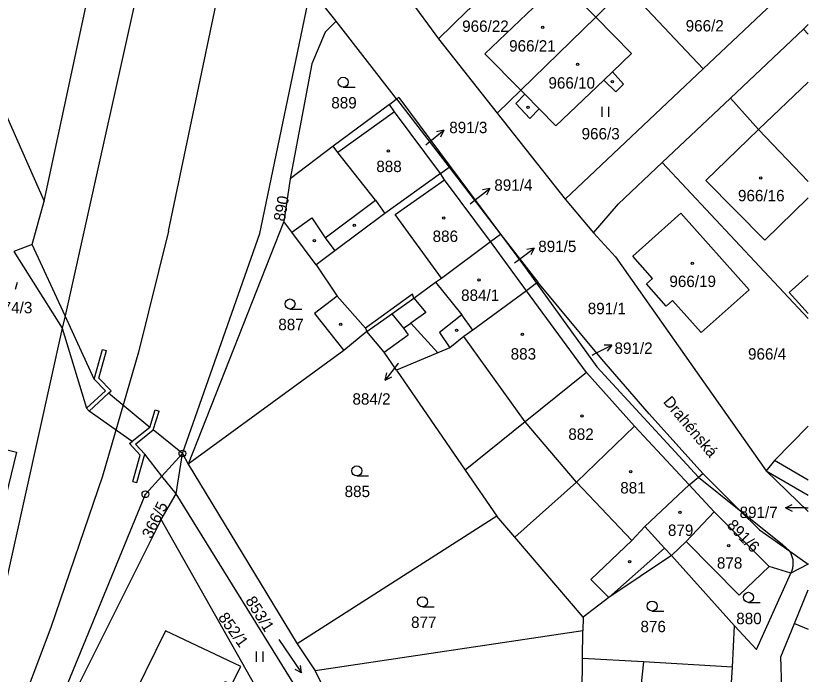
# Model space of a CAD drawing. Extents: x -776606 to -776076, y -974328 to -973875.
# Drawn here: x -776193.8 to -776075.5, y -974047.1 to -973948.9 of the extents above; entities that cross this region are included whole.
import ezdxf

# ---------------------------------------------------------------- set-up
doc = ezdxf.new("R2010")
doc.units = 0
for name, color, linetype in [('Hranice parcel', 7, 'Continuous'), ('Parcelní čísla', 7, 'Continuous'), ('Pop  PČ popisy', 7, 'Continuous'), ('Poz předměty', 7, 'Continuous'), ('Vnitřní kresba', 7, 'Continuous'), ('Značky bodu BP', 7, 'Continuous'), ('Značky budov', 7, 'Continuous'), ('Značky kultur', 7, 'Continuous')]:
    doc.layers.add(name, color=color, linetype=linetype)

msp = doc.modelspace()

# ---------------------------------------------------------------- linework, layer by layer
at = {"layer": 'Hranice parcel'}
for p, q in [((-776189.59, -973976.54), (-776179.58, -973929.94)), ((-776076.65, -973943.02), (-776091.19, -973956.75)), ((-776145.99, -973949.66), (-776149.78, -973944.77)), ((-776136.26, -973944.7), (-776130.7, -973952.3)), ((-776102.68, -973944.59), (-776107.23, -973949.03)), ((-776102.68, -973944.59), (-776091.19, -973956.75)), ((-776107.23, -973949.03), (-776118.42, -973959.96)), ((-776136.96, -973961.25), (-776145.99, -973949.66)), ((-776076.22, -973950.83), (-776075.52, -973950.16)), ((-776087.12, -973961.13), (-776076.22, -973950.83)), ((-776075.52, -973951.58), (-776076.22, -973950.83)), ((-776130.7, -973952.3), (-776121.93, -973963.39)), ((-776091.19, -973956.75), (-776111.8, -973976.22)), ((-776118.42, -973959.96), (-776121.93, -973963.39)), ((-776138, -973962.1), (-776136.96, -973961.25)), ((-776136.96, -973961.25), (-776129.11, -973971.44)), ((-776097.3, -973970.74), (-776087.12, -973961.13)), ((-776082.92, -973965.84), (-776087.12, -973961.13)), ((-776121.93, -973963.39), (-776111.8, -973976.22)), ((-776075.52, -973973.58), (-776082.92, -973965.84)), ((-776075.52, -973994.02), (-776097.3, -973970.74)), ((-776130.42, -973972.41), (-776129.11, -973971.44)), ((-776129.11, -973971.44), (-776121.45, -973981.44)), ((-776152.87, -973973.18), (-776153.8, -973979.55)), ((-776111.8, -973976.22), (-776107.56, -973981.25)), ((-776153.8, -973979.55), (-776168.07, -974015.77)), ((-776122.96, -973982.56), (-776121.45, -973981.44)), ((-776121.45, -973981.44), (-776115.88, -973988.61)), ((-776117.59, -973989.89), (-776122.96, -973982.56)), ((-776194.09, -973984.05), (-776186.87, -973995.48)), ((-776116.06, -973988.75), (-776117.59, -973989.89)), ((-776115.88, -973988.61), (-776116.06, -973988.75)), ((-776108.62, -974002.09), (-776117.59, -973989.89)), ((-776186.46, -973993.62), (-776186.87, -973995.48)), ((-776141.42, -973995.98), (-776137.69, -973993.34)), ((-776137.69, -973993.34), (-776135.91, -973995.5)), ((-776141.42, -973995.98), (-776144.84, -973998.83)), ((-776144.84, -973998.83), (-776168.07, -974015.77)), ((-776130.82, -973999.16), (-776136.99, -974001.76)), ((-776136.99, -974001.76), (-776126.7, -974016.67)), ((-776101.42, -974010.12), (-776108.62, -974002.09)), ((-776093.3, -974018.87), (-776101.42, -974010.12)), ((-776171.99, -974017.55), (-776168.94, -974014.19)), ((-776169.88, -974020.23), (-776168.94, -974014.19)), ((-776168.94, -974014.19), (-776168.07, -974015.77)), ((-776168.07, -974015.77), (-776151.82, -974042.59)), ((-776126.7, -974016.67), (-776121.97, -974023.54)), ((-776081.8, -974016.78), (-776075.52, -974020.41)), ((-776089.54, -974022.91), (-776093.3, -974018.87)), ((-776172.13, -974024.06), (-776169.88, -974020.23)), ((-776172.13, -974024.06), (-776193.76, -974067.27)), ((-776148.31, -974066.12), (-776172.13, -974024.06)), ((-776121.97, -974023.54), (-776151.82, -974042.59)), ((-776119.31, -974026.66), (-776121.97, -974023.54)), ((-776089.54, -974022.91), (-776093.73, -974027.35)), ((-776081.36, -974031.08), (-776089.54, -974022.91)), ((-776109.12, -974038.61), (-776119.31, -974026.66)), ((-776095.9, -974029.4), (-776093.73, -974027.35)), ((-776086.53, -974039.94), (-776095.9, -974029.4)), ((-776078.09, -974032.03), (-776081.36, -974031.08)), ((-776075.53, -974030.69), (-776078.09, -974032.03)), ((-776075.52, -974030.68), (-776075.53, -974030.69)), ((-776109.12, -974038.61), (-776109.14, -974040.66)), ((-776086.8, -974046.07), (-776086.53, -974039.94)), ((-776109.14, -974040.66), (-776149.12, -974046.61)), ((-776109.18, -974044.78), (-776109.14, -974040.66)), ((-776151.82, -974042.59), (-776149.12, -974046.61)), ((-776109.25, -974051.62), (-776109.18, -974044.78)), ((-776087.23, -974052.97), (-776086.8, -974046.07)), ((-776149.12, -974046.61), (-776143.9, -974057.28))]:
    msp.add_line(p, q, dxfattribs=at)
for points in [[(-776213.8, -973922.1), (-776202.27, -973939.42), (-776200.89, -973951.06), (-776189.59, -973976.54)], [(-776167.74, -973928.46), (-776173.47, -973935.17), (-776186.46, -973993.62)], [(-776130.7, -973952.3), (-776126.49, -973948.15), (-776111.76, -973934.97)], [(-776168.94, -974014.19), (-776157.37, -973981.34), (-776149.78, -973944.77)], [(-776107.23, -973949.03), (-776112.46, -973943.72), (-776115.35, -973946.49), (-776116.81, -973945.05), (-776117.87, -973946.03), (-776116.47, -973947.55), (-776123.77, -973954.53), (-776118.42, -973959.96)], [(-776107.23, -973949.03), (-776101.87, -973954.48), (-776104.75, -973957.23), (-776103.06, -973959.05), (-776104.22, -973960.21), (-776106.02, -973958.45), (-776113.17, -973965.28), (-776115.67, -973962.75), (-776117.06, -973964.17), (-776119.17, -973961.92), (-776117.83, -973960.56), (-776118.42, -973959.96)], [(-776145.99, -973949.66), (-776147.61, -973951.3), (-776149.59, -973956), (-776152.87, -973973.18)], [(-776082.92, -973965.84), (-776075.52, -973958.78)], [(-776138, -973962.1), (-776146.44, -973968.3), (-776152.87, -973973.18)], [(-776130.42, -973972.41), (-776137.25, -973963.2), (-776138, -973962.1)], [(-776075.52, -973976.03), (-776082, -973982.35), (-776090.8, -973973.46), (-776082.92, -973965.84)], [(-776107.56, -973981.25), (-776103.85, -973976.92), (-776097.3, -973970.74)], [(-776130.42, -973972.41), (-776138.73, -973978.35), (-776146.16, -973983.93), (-776148.95, -973986.03)], [(-776122.96, -973982.56), (-776129.81, -973973.34), (-776130.42, -973972.41)], [(-776186.46, -973993.62), (-776191.35, -973982.98), (-776189.59, -973976.54)], [(-776095.76, -973991.37), (-776096.7, -973992.2), (-776099.67, -973988.88), (-776098.73, -973988.05), (-776101.7, -973984.72), (-776094.53, -973978.32), (-776084.33, -973989.75), (-776091.49, -973996.15), (-776095.76, -973991.37)], [(-776148.95, -973986.03), (-776152.6, -973981.15), (-776153.8, -973979.55)], [(-776107.56, -973981.25), (-776104.28, -973984.85), (-776081.8, -974016.78)], [(-776137.69, -973993.34), (-776134.4, -973991), (-776131.15, -973988.6), (-776130.25, -973988), (-776122.96, -973982.56)], [(-776148.95, -973986.03), (-776145.82, -973990.7), (-776149.23, -973993.27), (-776144.84, -973998.83)], [(-776075.52, -973993.3), (-776078.33, -973990.14), (-776075.52, -973987.63)], [(-776091.25, -974017.2), (-776099.26, -974008.29), (-776106.34, -974000.13), (-776115.88, -973988.61)], [(-776117.59, -973989.89), (-776125.6, -973995.78), (-776126.92, -973996.73), (-776129, -973998.4), (-776130.82, -973999.16)], [(-776186.87, -973995.48), (-776195.9, -974036.12), (-776202.98, -974064.31), (-776215.3, -974064.46)], [(-776135.91, -973995.5), (-776134.85, -973994.75), (-776130.82, -973999.16)], [(-776136.99, -974001.76), (-776138.84, -973999.06), (-776141.42, -973995.98)], [(-776108.62, -974002.09), (-776117.78, -974009.48), (-776126.7, -974016.67)], [(-776101.42, -974010.12), (-776110.09, -974018.45), (-776119.31, -974026.66)], [(-776075.52, -974010.09), (-776080.54, -974015.24), (-776081.8, -974016.78)], [(-776196.71, -974013.25), (-776193.7, -974014), (-776195.7, -974022.19), (-776199.27, -974021.29)], [(-776075.52, -974022.83), (-776081.8, -974016.78)], [(-776193.76, -974067.27), (-776174.47, -974020.28), (-776171.99, -974017.55)], [(-776093.3, -974018.87), (-776091.91, -974017.74), (-776091.25, -974017.2)], [(-776091.25, -974017.2), (-776085.79, -974022.61), (-776082.79, -974025.58), (-776078.27, -974028.77), (-776075.53, -974030.69)], [(-776093.3, -974018.87), (-776099.9, -974025.1), (-776096.95, -974028.3), (-776095.9, -974029.4)], [(-776146.2, -974065.84), (-776150.23, -974051.95), (-776169.88, -974020.23)], [(-776093.73, -974027.35), (-776085.8, -974035.35), (-776081.36, -974031.08)], [(-776095.9, -974029.4), (-776105.28, -974035.69), (-776109.12, -974038.61)], [(-776086.53, -974039.94), (-776083.24, -974043.46), (-776078.09, -974032.03)], [(-776079.28, -974053.91), (-776079.58, -974044.52), (-776077.53, -974039.59), (-776075.52, -974034.53)], [(-776171.44, -974040.68), (-776177.4, -974052.7), (-776167.44, -974057.5), (-776162.53, -974048.25), (-776161.63, -974048.7), (-776160.2, -974046), (-776171.44, -974040.68)], [(-776086.8, -974046.07), (-776100.12, -974045.3), (-776109.18, -974044.78)]]:
    msp.add_lwpolyline(points, dxfattribs=at)
at = {"layer": 'Pop  PČ popisy'}
for p, q in [((-776132.26, -973967.82), (-776129.93, -973965.93)), ((-776129.93, -973965.93), (-776131.02, -973966.17)), ((-776129.93, -973965.93), (-776130.39, -973966.95)), ((-776132.61, -973968.11), (-776132.26, -973967.82)), ((-776125.41, -973976.46), (-776123.05, -973974.61)), ((-776123.05, -973974.61), (-776124.14, -973974.83)), ((-776123.05, -973974.61), (-776123.53, -973975.62)), ((-776125.99, -973976.91), (-776125.41, -973976.46)), ((-776118.82, -973985.33), (-776116.42, -973983.52)), ((-776116.42, -973983.52), (-776117.52, -973983.73)), ((-776116.42, -973983.52), (-776116.92, -973984.53)), ((-776119.37, -973985.75), (-776118.82, -973985.33)), ((-776193.87, -973989.68), (-776193.58, -973988.59)), ((-776107.52, -973999.38), (-776104.85, -973998.02)), ((-776104.85, -973998.02), (-776105.97, -973998.03)), ((-776104.85, -973998.02), (-776105.51, -973998.92)), ((-776107.77, -973999.51), (-776107.52, -973999.38)), ((-776136.81, -974000.87), (-776138.66, -974003.23)), ((-776136.69, -974000.72), (-776136.81, -974000.87)), ((-776138.66, -974003.23), (-776138.44, -974002.14)), ((-776138.66, -974003.23), (-776137.65, -974002.75)), ((-776078.89, -974022.31), (-776077.89, -974021.81)), ((-776075.89, -974022.31), (-776078.89, -974022.31)), ((-776078.89, -974022.31), (-776077.89, -974022.81)), ((-776075.89, -974022.31), (-776075.52, -974022.31))]:
    msp.add_line(p, q, dxfattribs=at)
at = {"layer": 'Poz předměty'}
for p, q in [((-776170.99, -973981), (-776163.09, -973943.22)), ((-776170.99, -973981), (-776175.48, -973999.05)), ((-776175.48, -973999.05), (-776180.85, -974017.57)), ((-776180.85, -974017.57), (-776188.57, -974040.14)), ((-776188.57, -974040.14), (-776193.46, -974053.03))]:
    msp.add_line(p, q, dxfattribs=at)
at = {"layer": 'Vnitřní kresba'}
for p, q in [((-776106.02, -973958.45), (-776104.75, -973957.23)), ((-776136.65, -973961.05), (-776136.96, -973961.25)), ((-776136.65, -973961.05), (-776121.45, -973981.44)), ((-776117.83, -973960.56), (-776115.67, -973962.75)), ((-776137.25, -973963.2), (-776145.71, -973969.26)), ((-776145.71, -973969.26), (-776146.44, -973968.3)), ((-776140.13, -973976.39), (-776145.71, -973969.26)), ((-776137.17, -973978.5), (-776129.81, -973973.34)), ((-776147.6, -973982.01), (-776140.13, -973976.39)), ((-776140.13, -973976.39), (-776138.73, -973978.35)), ((-776152.6, -973981.15), (-776149.6, -973979)), ((-776149.6, -973979), (-776147.6, -973982.01)), ((-776130.25, -973988), (-776137.17, -973978.5)), ((-776121.45, -973981.44), (-776117.69, -973986.48)), ((-776147.6, -973982.01), (-776146.16, -973983.93)), ((-776191.35, -973982.98), (-776194.09, -973984.05)), ((-776117.69, -973986.48), (-776116.06, -973988.75)), ((-776131.15, -973988.6), (-776127.2, -973993.5)), ((-776116.06, -973988.75), (-776107.08, -974001.25)), ((-776141.61, -973995.5), (-776145.82, -973990.7)), ((-776134.6, -973990.4), (-776141.61, -973995.5)), ((-776134.4, -973991), (-776134.6, -973990.4)), ((-776134.4, -973991), (-776132.61, -973993.15)), ((-776132.61, -973993.15), (-776134.85, -973994.75)), ((-776182.09, -974003.11), (-776186.46, -973993.62)), ((-776127.2, -973993.5), (-776130.55, -973996.11)), ((-776125.6, -973995.78), (-776127.2, -973993.5)), ((-776186.87, -973995.48), (-776183.28, -974007.42)), ((-776141.61, -973995.5), (-776141.42, -973995.98)), ((-776135.91, -973995.5), (-776135.21, -973996.48)), ((-776138.84, -973999.06), (-776135.21, -973996.48)), ((-776130.55, -973996.11), (-776129, -973998.4)), ((-776117.78, -974009.48), (-776126.92, -973996.73)), ((-776182.09, -974003.11), (-776180.87, -973998.66)), ((-776181.42, -974002.94), (-776180.29, -973998.82)), ((-776180.87, -973998.66), (-776180.29, -973998.82)), ((-776091.91, -974017.74), (-776107.08, -974001.25)), ((-776182.09, -974003.11), (-776180.43, -974004.81)), ((-776179.57, -974004.83), (-776181.42, -974002.94)), ((-776180.43, -974004.81), (-776183.28, -974007.42)), ((-776179.96, -974005.2), (-776179.57, -974004.83)), ((-776182.87, -974007.86), (-776179.96, -974005.2)), ((-776173.81, -974010.32), (-776179.96, -974005.2)), ((-776183.28, -974007.42), (-776182.87, -974007.86)), ((-776176.44, -974012.41), (-776182.87, -974007.86)), ((-776173.81, -974010.32), (-776172.98, -974007.68)), ((-776173.29, -974010.68), (-776172.41, -974007.86)), ((-776172.98, -974007.68), (-776172.41, -974007.86)), ((-776110.09, -974018.45), (-776117.78, -974009.48)), ((-776173.81, -974010.32), (-776176.44, -974012.41)), ((-776175.94, -974012.78), (-776173.29, -974010.68)), ((-776168.94, -974014.19), (-776173.29, -974010.68)), ((-776176.82, -974012.71), (-776176.44, -974012.41)), ((-776176.82, -974012.71), (-776175.24, -974014.44)), ((-776174.57, -974014.28), (-776175.94, -974012.78)), ((-776176.34, -974018.36), (-776175.24, -974014.44)), ((-776175.76, -974018.52), (-776174.57, -974014.28)), ((-776171.99, -974017.55), (-776174.57, -974014.28)), ((-776075.52, -974018.18), (-776080.54, -974015.24)), ((-776169.88, -974020.23), (-776171.99, -974017.55)), ((-776091.91, -974017.74), (-776085.79, -974022.61)), ((-776176.34, -974018.36), (-776175.76, -974018.52)), ((-776110.09, -974018.45), (-776101.85, -974027.2)), ((-776085.79, -974022.61), (-776079.38, -974027.71)), ((-776101.85, -974027.2), (-776099.9, -974025.1)), ((-776107.95, -974033), (-776101.85, -974027.2)), ((-776096.95, -974028.3), (-776105.28, -974035.69)), ((-776079.38, -974027.71), (-776078.27, -974028.77)), ((-776105.28, -974035.69), (-776107.95, -974033)), ((-776077.53, -974039.59), (-776075.52, -974040.39)), ((-776100.12, -974045.3), (-776100.85, -974052.03))]:
    msp.add_line(p, q, dxfattribs=at)
msp.add_lwpolyline([(-776078.09, -974032.03), (-776078.02, -974031.89), (-776077.96, -974031.75), (-776077.91, -974031.6), (-776077.86, -974031.45), (-776077.82, -974031.3), (-776077.79, -974031.15), (-776077.77, -974031), (-776077.75, -974030.84), (-776077.74, -974030.69), (-776077.74, -974030.53), (-776077.74, -974030.38), (-776077.75, -974030.22), (-776077.77, -974030.07), (-776077.8, -974029.91), (-776077.83, -974029.76), (-776077.88, -974029.61), (-776077.93, -974029.46), (-776077.98, -974029.32), (-776078.04, -974029.18), (-776078.11, -974029.04), (-776078.19, -974028.9), (-776078.27, -974028.77)], dxfattribs=at)
at = {"layer": 'Značky bodu BP'}
for centre, radius in [((-776168.94, -974014.19), 0.5), ((-776168.94, -974014.19), 0.0303), ((-776174.47, -974020.28), 0.5), ((-776174.47, -974020.28), 0.0303)]:
    msp.add_circle(centre, radius, dxfattribs=at)
at = {"layer": 'Značky budov'}
for centre in [(-776115.13, -973950.58), (-776109.95, -973956.11), (-776104.74, -973958.7), (-776117.34, -973962.49), (-776138.19, -973969.02), (-776082.6, -973973.05), (-776129.91, -973979.04), (-776143.28, -973980.12), (-776149.22, -973982.41), (-776092.82, -973985.78), (-776124.64, -973988.27), (-776145.29, -973994.92), (-776128, -973995.8), (-776118.17, -973996.38), (-776109.27, -974008.57), (-776102, -974016.9), (-776094.67, -974022.98), (-776087.38, -974027.97), (-776102.17, -974030.34)]:
    msp.add_circle(centre, 0.175, dxfattribs=at)
at = {"layer": 'Značky kultur'}
for p, q in [((-776144.92, -973959.52), (-776143.17, -973959.52)), ((-776106.27, -973963.92), (-776106.27, -973962.42)), ((-776105.27, -973963.92), (-776105.27, -973962.42)), ((-776152.87, -973992.62), (-776151.12, -973992.62)), ((-776142.89, -974017.54), (-776141.14, -974017.54)), ((-776133.1, -974037.07), (-776131.35, -974037.07)), ((-776084.43, -974036.41), (-776082.68, -974036.41)), ((-776098.81, -974037.71), (-776097.06, -974037.71)), ((-776154.52, -974041.96), (-776151.16, -974046.94)), ((-776157.9, -974045.27), (-776157.9, -974043.77)), ((-776156.9, -974045.27), (-776156.9, -974043.77)), ((-776151.16, -974046.94), (-776152.12, -974046.41)), ((-776151.16, -974046.94), (-776151.29, -974045.85))]:
    msp.add_line(p, q, dxfattribs=at)
for centre in [(-776144.92, -973958.77), (-776152.87, -973991.87), (-776142.89, -974016.79), (-776133.1, -974036.32), (-776084.43, -974035.66), (-776098.81, -974036.96)]:
    msp.add_circle(centre, 0.75, dxfattribs=at)

# ---------------------------------------------------------------- texts
at = {"layer": 'Parcelní čísla'}
for s, p in [('966/22', (-776127.17, -973951.25)), ('966/2', (-776093.8, -973951.19)), ('966/21', (-776120.16, -973954.19)), ('966/10', (-776114.29, -973959.72)), ('889', (-776146.71, -973962.68)), ('891/3', (-776129.1, -973966.37)), ('966/3', (-776109.34, -973967.3)), ('888', (-776139.99, -973972.18)), ('891/4', (-776122.37, -973974.97)), ('966/16', (-776085.99, -973976.54)), ('886', (-776131.58, -973982.61)), ('891/5', (-776115.81, -973984.12)), ('966/19', (-776096.23, -973989.34)), ('884/1', (-776127.33, -973991.41)), ('774/3', (-776197.03, -973993.26)), ('891/1', (-776108.42, -973993.39)), ('887', (-776154.62, -973995.78)), ('891/2', (-776104.43, -973999.32)), ('883', (-776119.93, -974000.17)), ('966/4', (-776084.49, -974000.18)), ('884/2', (-776143.55, -974006.9)), ('882', (-776111.32, -974012.15)), ('885', (-776144.72, -974020.7)), ('881', (-776103.57, -974020.16)), ('891/7', (-776085.75, -974023.82)), ('879', (-776096.45, -974026.49)), ('878', (-776089.14, -974031.38)), ('880', (-776086.25, -974039.67)), ('877', (-776134.8, -974040.23)), ('876', (-776100.55, -974040.87))]:
    msp.add_text(s, height=1.7, dxfattribs=at).set_placement(p)
for s, rotation, p in [('890', 80, (-776153.67, -973979.63)), ('366/5', 64, (-776173.55, -974027.03)), ('891/6', 314, (-776087.77, -974025.02)), ('853/1', 302, (-776159.6, -974036.16)), ('852/1', 306, (-776163.69, -974038.68))]:
    msp.add_text(s, height=1.7, rotation=rotation, dxfattribs=at).set_placement(p)
at = {"layer": 'Pop  PČ popisy'}
msp.add_text('Drahénská', height=1.7, rotation=310, dxfattribs=at).set_placement((-776097.25, -974006.51))

doc.saveas('drawing.dxf')
